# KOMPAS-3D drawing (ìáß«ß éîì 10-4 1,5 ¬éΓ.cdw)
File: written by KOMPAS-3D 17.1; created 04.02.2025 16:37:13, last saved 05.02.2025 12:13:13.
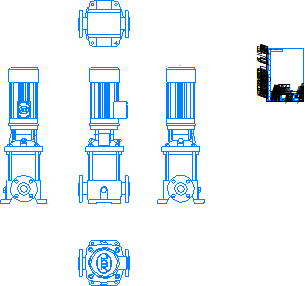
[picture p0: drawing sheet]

Sheet 1: A4, portrait

Title block, sheet 1: name: Насос ВМН 10-4 1,5 / кВт; designation: Насос ВМН 10-4 1,5 кВт; material: Сталь 10  ГОСТ 1050-2013; mass: 129,14; sheets: 1; sheet format: A4; stored path: \\adlc.lan\data\АДЛ_ПКД\3D-модели\ADL production\Насосы ГРАНПАМП\Насосы ВМН\ВМН10\KOMPAS 3D\Насос ВМН 10-4 1,5 кВт.cdw

Views: Вид 1, Спереди, Проекционный вид 2, Проекционный вид 3, Проекционный вид 4, Проекционный вид 5
Referenced files in \\adlc.lan\data\АДЛ_ПКД\3D-модели\ADL production\Насосы ГРАНПАМП\Насосы ВМН\ВМН10\KOMPAS 3D\: ВМН 10-4 1,5 кВт.m3d, Насос ВМН 10-4 1,5 кВт.m3d
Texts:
  Andrey
  АДЛ
Dimensions and other numbers on the sheet: 1:1; 1; 129,14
